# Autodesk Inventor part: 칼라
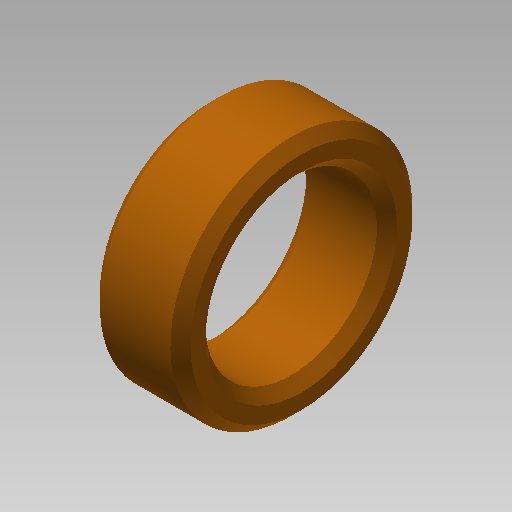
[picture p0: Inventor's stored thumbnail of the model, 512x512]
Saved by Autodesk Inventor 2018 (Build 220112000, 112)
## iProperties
Created: 2016-10
Part Number: 칼라
Material: 강철, 연강
Document SubType Name: Modeling
Designer: mduedu
Density: 1 g/cm^3
Appearance: 주황색
Author: mduedu
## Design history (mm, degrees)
sketch "스케치1"
  geometry: C1 r 12 at (0, 0); C2 r 8.5 at (0, 0); 1 further point
  constraints: 2 centre point, 2 coincident
  dimensions: "d0" = 24 diameter of C1; "d1" = 17 diameter of C2
extrude "돌출1" new body sketch "스케치1" distance "d2" = 9; taper "d3" = 0 deg
chamfer "모따기1" distance "d4" = 1; stored, may be unused: second distance "d5" = 2, angle "d6" = 45 deg
node "솔리드1"
